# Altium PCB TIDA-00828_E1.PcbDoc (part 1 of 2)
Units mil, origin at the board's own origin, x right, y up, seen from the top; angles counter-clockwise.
Board outline 3410 x 2125 mil, 4 copper layers (Top Layer, Signal Layer 1, Signal Layer 2, Bottom Layer), stack 61.6 mil thick; 60 components, 54 nets, 228 pads, 108 vias.
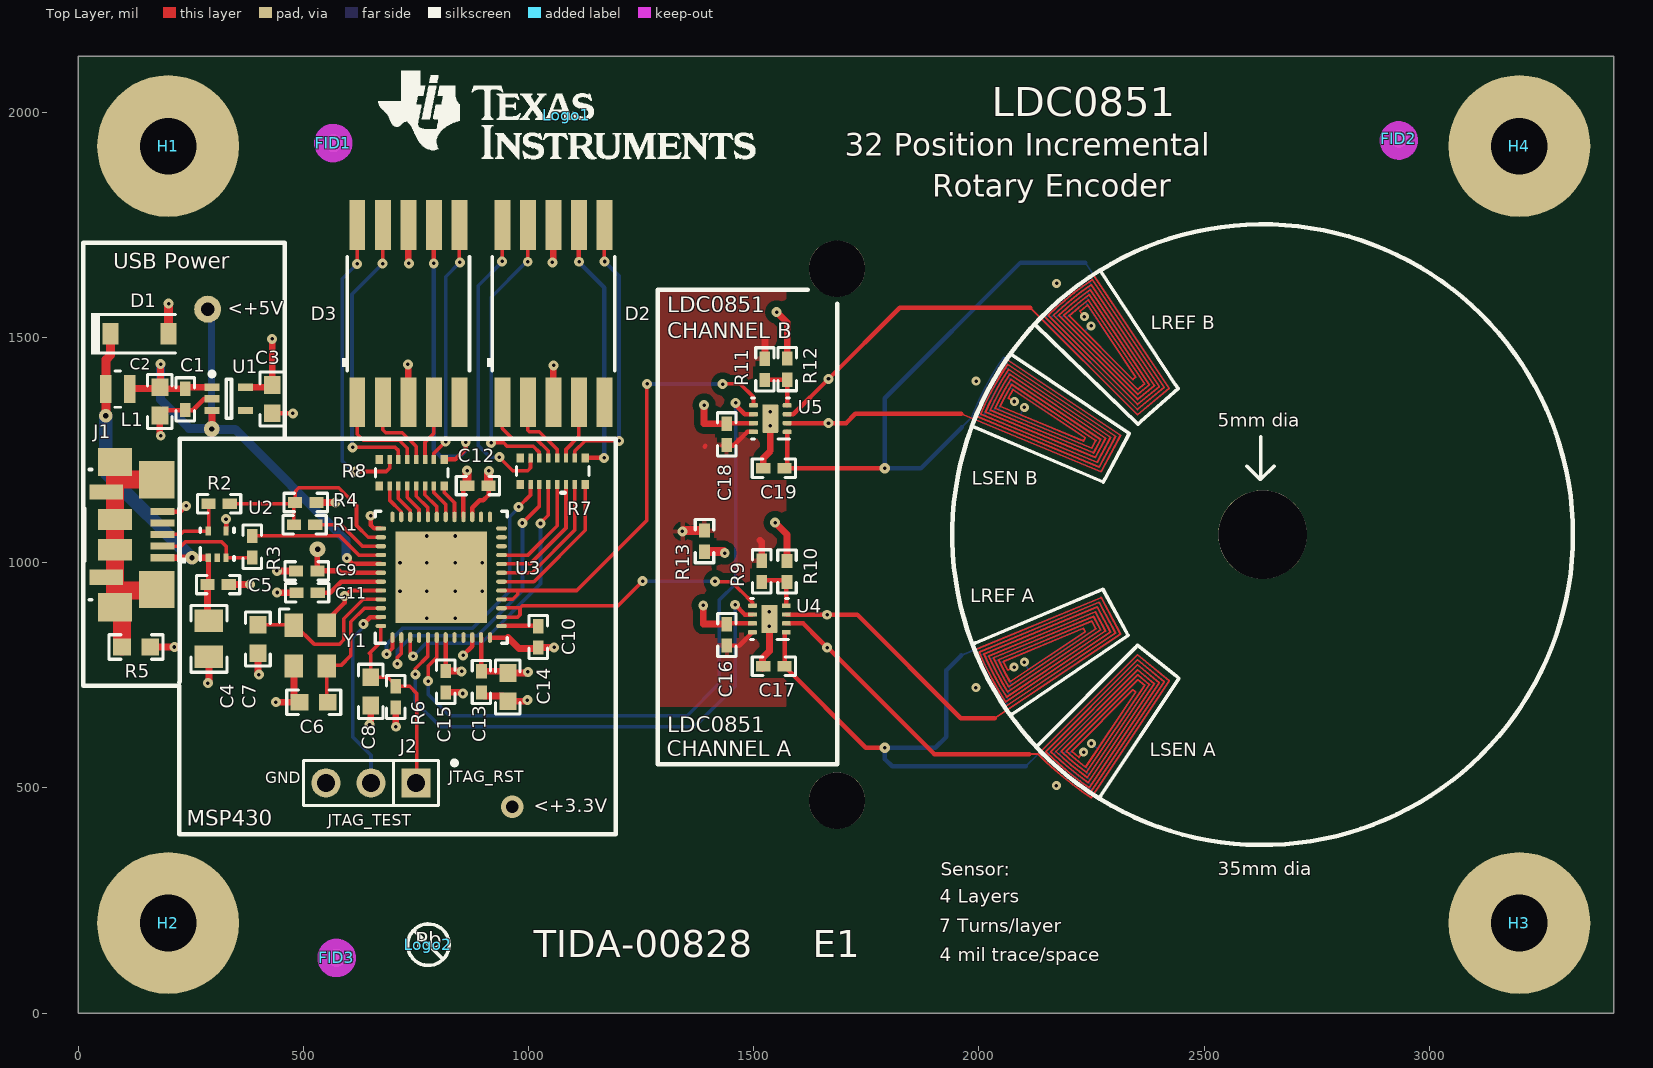
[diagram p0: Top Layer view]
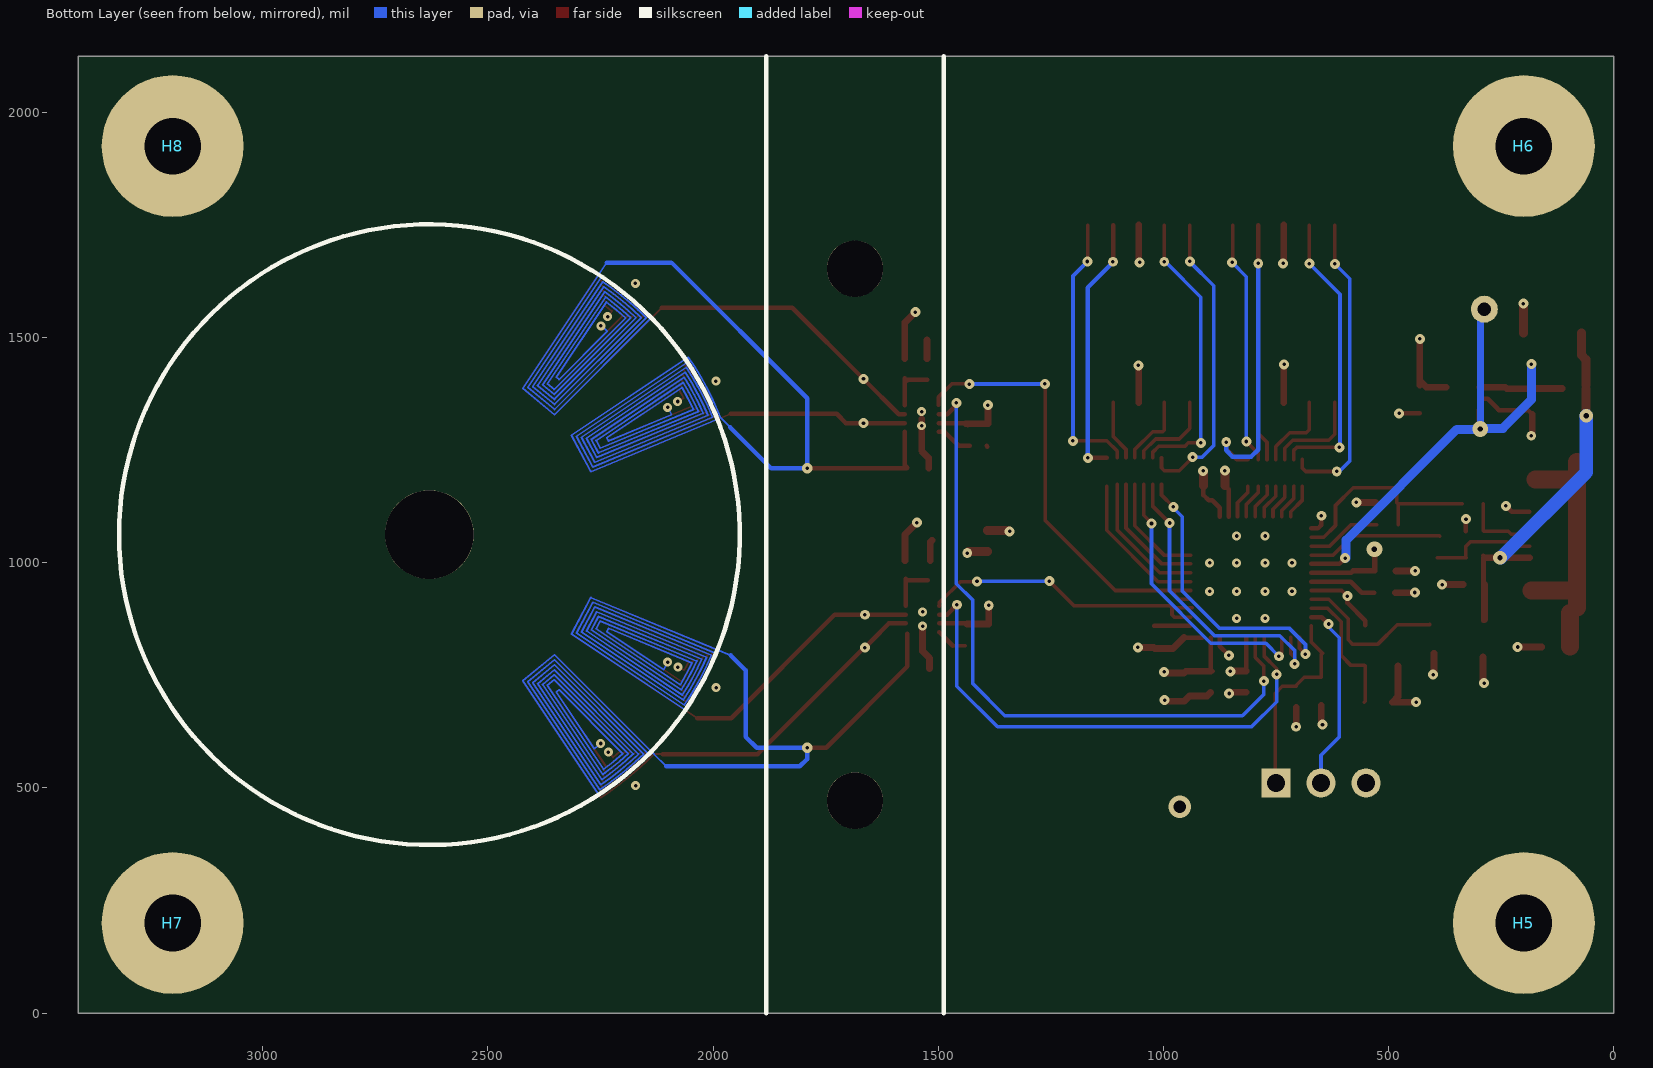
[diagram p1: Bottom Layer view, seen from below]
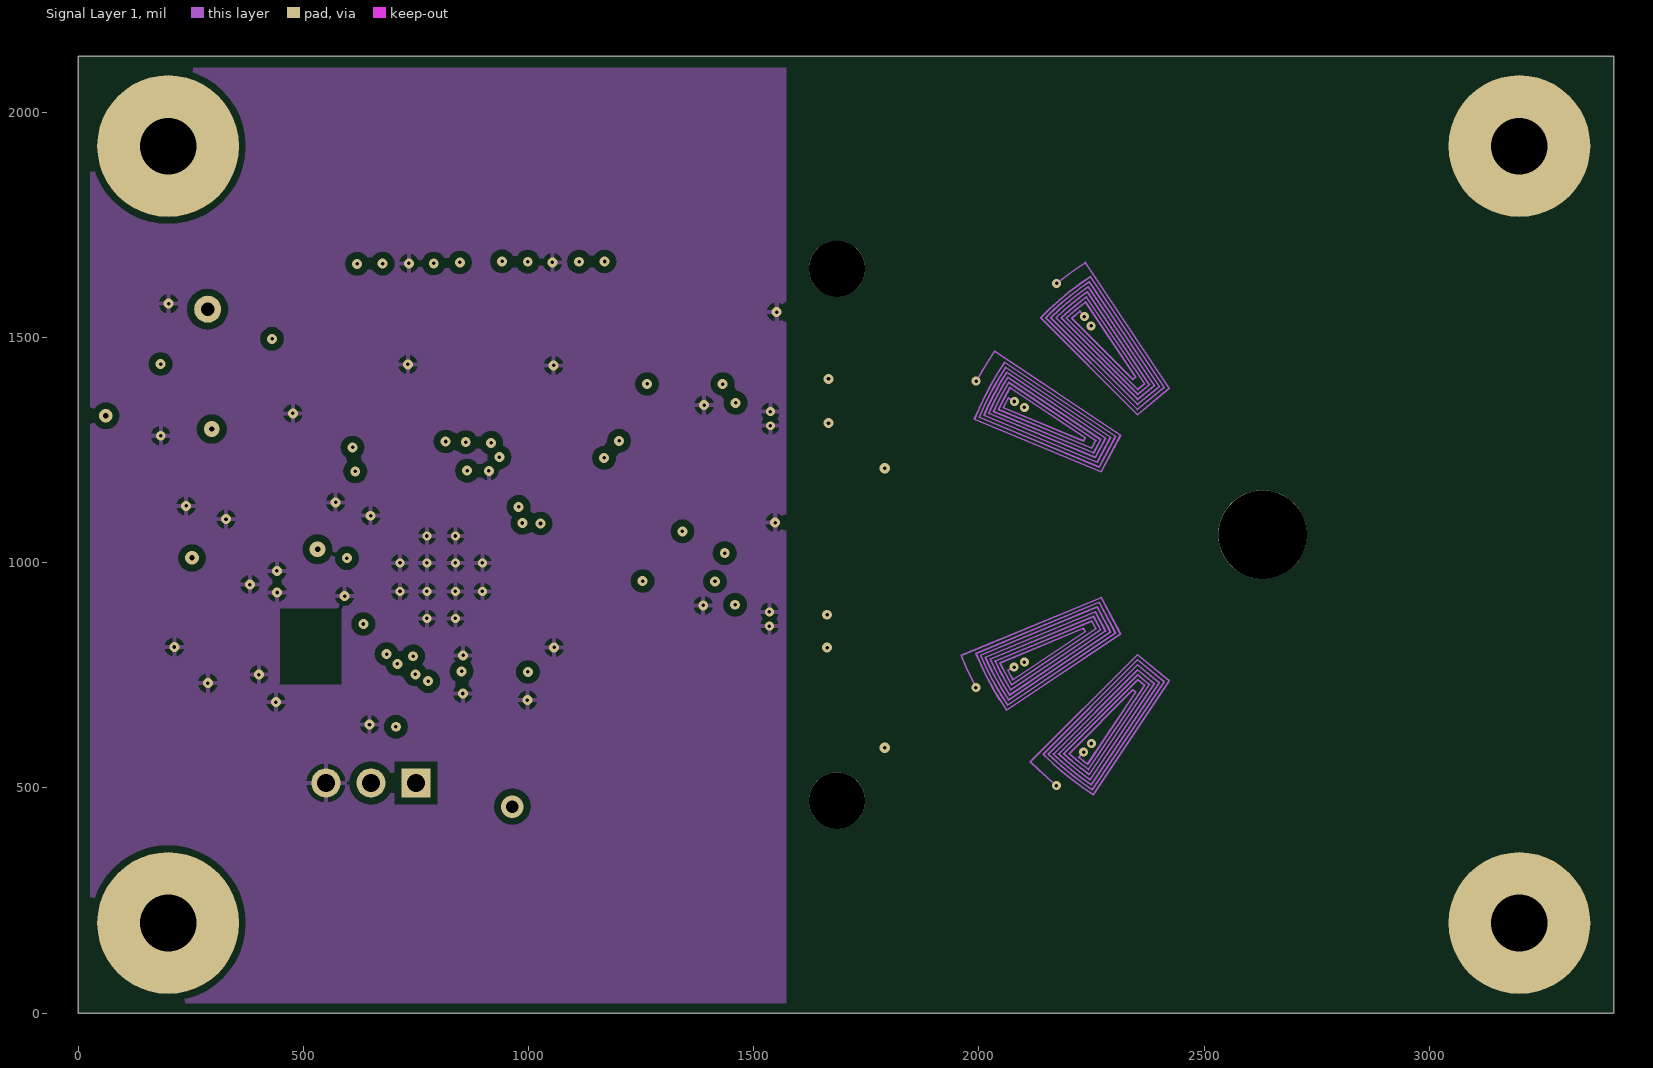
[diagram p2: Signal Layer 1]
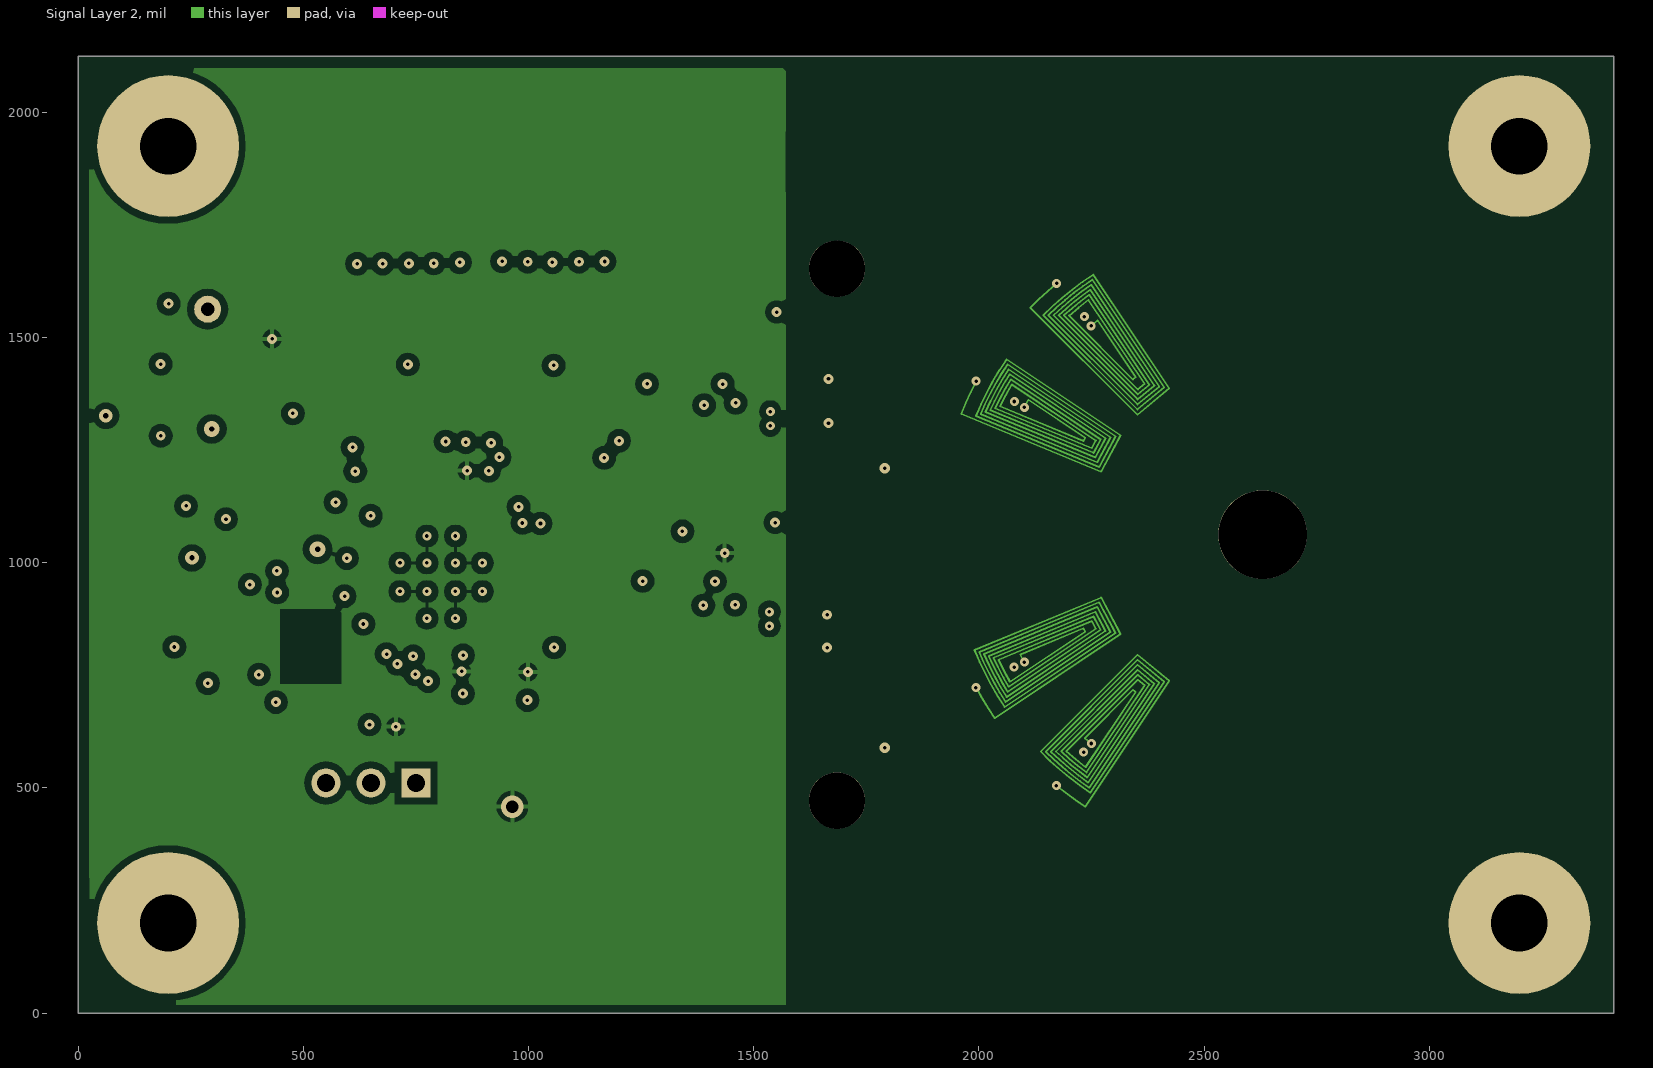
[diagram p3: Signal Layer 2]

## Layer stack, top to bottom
Top Solder: solder mask 0.4, Solder Resist, Dk 3.5
Top Layer: signal copper 1.4
Dielectric 1: core 10, FR-4, Dk 4.1
Signal Layer 1: signal copper 1.4
Dielectric 2: prepreg 36, FR-4, Dk 4.1
Signal Layer 2: signal copper 1.4
Dielectric 3: core 10, FR-4, Dk 4.1
Bottom Layer: signal copper 1.4
Bottom Solder: solder mask 0.4, Solder Resist, Dk 3.5

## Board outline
0,0 3410,0 3410,2125 0,2125

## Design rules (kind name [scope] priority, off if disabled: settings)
AcuteAngle [All] p1: minimum=4.50000000000000E+0001 checktracksonly=FALSE
AssemblyTestPointUsage [All] p1: valid=2
Clearance Clearance_Keepouts [((IsTrack Or IsArc) And Not InPoly) And IsFree and IsKeepOut vs ((IsTrack Or IsArc) And Not InPoly) And IsFree and IsKeepOut] p1: gap=0
Clearance Clearance_BoardEdge_MountingHoles [OnCopper and InComponentClass('Mounting Holes') vs IsKeepOut] p2: gap=40
Clearance Clearance_BoardEdge_Poly [OnCopper and InPoly vs IsKeepOut] p3: gap=25
Clearance Clearance_BoardEdge [OnCopper and Not InComponentClass('Logo') and not InComponentClass('FiducialMark') and not InRegion(1000,500,4000,800) and Not IsKeepout vs IsKeepOut] p4: gap=25
Clearance Clearance_Poly [InPolygon] p5: gap=15
Clearance [All] p6: gap=8 except(7: SMDPad-SMDPad)
ComponentClearance ComponentClearance_MountingHoles_FiducialMarks [InComponentClass('Mounting Holes') vs InComponentClass('FiducialMark')] p1: gap=50 collisioncheckmode=3 verticalgap=10 showdistances=FALSE
ComponentClearance ComponentClearance_Shunt [InComponentClass('Header') vs InComponentClass('Shunt')] p2: gap=0 collisioncheckmode=3 verticalgap=0 showdistances=FALSE
ComponentClearance ComponentClearance_Logo [InComponentClass('Logo')] p3: gap=50 collisioncheckmode=3 verticalgap=10 showdistances=FALSE
ComponentClearance ComponentClearance_ScrewToNut [(HasFootprint('NY PMS 440 0025 PH')) vs (HasFootprint('Keystone_1902C'))] p4: gap=5 collisioncheckmode=3 verticalgap=10 showdistances=FALSE
ComponentClearance ComponentClearance_MountingHoles [InComponentClass('Mounting Holes')] p5: gap=250 collisioncheckmode=3 verticalgap=100000 showdistances=FALSE
ComponentClearance ComponentClearance_SmallPassives [HasFootprint('0201*') or HasFootprint('0402*') or HasFootprint('0508') or HasFootprint('0603*') or HasFootprint('0612') or HasFootprint('0805*') or HasFootprint('0815*') or HasFootprint('0830*') or HasFootprint('1206*') or HasFootprint('1210*') or HasFootprint('1808*') or HasFootprint('1812*') or HasFootprint('1825*') or HasFootprint('2010*') or HasFootprint('2220*') or HasFootprint('2225*') or HasFootprint('2512*') or HasFootprint('2728*') or HasFootprint('3518*') vs HasFootprint('0201*') or HasFootprint('0402*') or HasFootprint('0508') or HasFootprint('0603*') or HasFootprint('0612') or HasFootprint('0805*') or HasFootprint('0815*') or HasFootprint('0830*') or HasFootprint('1206*') or HasFootprint('1210*') or HasFootprint('1808*') or HasFootprint('1812*') or HasFootprint('1825*') or HasFootprint('2010*') or HasFootprint('2220*') or HasFootprint('2225*') or HasFootprint('2512*') or HasFootprint('2728*') or HasFootprint('3518*')] p6: gap=20 collisioncheckmode=3 verticalgap=10 showdistances=FALSE
ComponentClearance ComponentClearance_THtoSMT [IsThruComponent vs IsSMTComponent] p7: gap=100 collisioncheckmode=3 verticalgap=30 showdistances=FALSE
ComponentClearance ComponentClearance_THtoTH [IsThruComponent vs IsThruComponent] p8: gap=118.11 collisioncheckmode=3 verticalgap=30 showdistances=FALSE
ComponentClearance [All] p9: gap=30 collisioncheckmode=3 verticalgap=10 showdistances=FALSE
DiffPairsRouting [All] p1: maxlimit=100 minlimit=10 mostfreqgap=10 toplayer_minwidth=15 toplayer_maxwidth=15 toplayer_prefwidth=15 midlayer1_minwidth=15 midlayer1_maxwidth=15 midlayer1_prefwidth=15 midlayer2_minwidth=15 midlayer2_maxwidth=15 midlayer2_prefwidth=15 bottomlayer_minwidth=15 bottomlayer_maxwidth=15 bottomlayer_prefwidth=15 maxuncoupledlength=1000
FabricationTestPointUsage TestPointUsage [All] p1: valid=2 allowmultiple=FALSE
FabricationTestpoint Testpoint [All] p1: side=3 testpointundercomponent=TRUE minsize=40 maxsize=100 preferedsize=60 minholesize=0 maxholesize=40 preferedholesize=32 testpointgrid=1 allowsidetop=TRUE allowsidebottom=TRUE usegrid=TRUE gridtolerance=0.01
FanoutControl Fanout_LCC [IsLCC] p1: bgadir=Out bgaviamode=Centered fanoutstyle=Auto fanoutdirection=Alternating viagrid=1 // Fanout_LCC (Default Rule)
FanoutControl Fanout_BGA [IsBGA] p2: bgadir=Out bgaviamode=Centered fanoutstyle=Auto fanoutdirection=Alternating viagrid=1 // Fanout_BGA (Default Rule)
FanoutControl Fanout_Default [All] p4: bgadir=Out bgaviamode=Centered fanoutstyle=Auto fanoutdirection=Alternating viagrid=1 // Fanout_Default (Default Rule)
FanoutControl Fanout_Small [(CompPinCount < 5)] p5: bgadir=Out bgaviamode=Centered fanoutstyle=Auto fanoutdirection=OutThenIn viagrid=1 // Fanout_Small (Default Rule)
HoleSize [All] p1: absolutevalues=TRUE maxlimit=251 minlimit=8 maxpercent=80.000 minpercent=20.000
MinimumAnnularRing MinimumAnnularRing_ThermalPadVias [IsVia and InAnyComponent] p1: minimumring=5.91
MinimumAnnularRing [All] p2: minimumring=6
MinimumSolderMaskSliver MinimumSolderMaskSliver_Logo [InComponentClass('Logo') vs InComponentClass('Logo')] p1: minsoldermaskwidth=0.7
MinimumSolderMaskSliver [All] p2: minsoldermaskwidth=3.94
PlaneConnect [All] p1: planeconnectstyle=Relief reliefexpansion=10 reliefentries=4 reliefconductorwidth=10 reliefairgap=10
PolygonConnect [All] p1: connectstyle=Relief reliefconductorwidth=10 reliefentries=4 polygonreliefangle="90 Angle" airgapwidth=10
RoutingVias ThermalPadVias [IsVia and InAnyComponent] p1: holewidth=7.87 width=19.68 viastyle="Through Hole" minholewidth=7.87 minwidth=19.68 maxholewidth=12.99 maxwidth=23.62
RoutingVias [All] p2: holewidth=8 width=22 viastyle="Through Hole" minholewidth=7.87 minwidth=20 maxholewidth=40 maxwidth=65
SilkToBoardRegionClearance [Not ((IsComment or IsDesignator) And (Hide <> 'False')) and not InRegion(1000,500,4000,800)] p1:
SilkToSilkClearance SilkToSilkClearance_Pb-FreeLogo [(HasFootprint('Pb-Free_Overlay_Medium') OR HasFootprint('Pb-Free_Overlay_Small')) vs (HasFootprint('Pb-Free_Overlay_Medium') OR HasFootprint('Pb-Free_Overlay_Small'))] p1: silktosilkclearance=0
SilkToSilkClearance [All] p2: silktosilkclearance=4
SilkToSolderMaskClearance SilkToComonentPadClearance [IsPad and InAnycomponent] p1: minsilkscreentomaskgap=1 clearancetoexposedcopper=TRUE
SilkToSolderMaskClearance "Silk to Solder Mask Opening" [All] p2: minsilkscreentomaskgap=1 clearancetoexposedcopper=FALSE
SolderMaskExpansion [All] p1: expansion=1.97
UnpouredPolygon [All] p1: allowunpoured=FALSE
Width [All] p1: maxlimit=100 minlimit=4 preferedwidth=8 minimp=50.000000 maximp=50.000000 favimp=50.000000 checkconnectedcopper=TRUE
14 further rules are at their usual default settings.

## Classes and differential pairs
component class "Mounting Holes": H1 H2 H3 H4
component class Header: J2
component class Logo: Logo1
component class FiducialMark: FID1 FID2 FID3
component class AssemblyNote: ZZ1 ZZ2 ZZ3

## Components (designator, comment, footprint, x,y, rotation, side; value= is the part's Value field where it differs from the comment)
C1 "GRM155R71C104JA88D" 0402 237.8,1362.73 r270 top
C2 "C1608X5R1A106M" 0603 181.61,1358.34 r270 top
C3 "C0603C225K8PACTU" 0603 431.14,1363.24 r270 top
C4 "C2012X5R1C226K125AC" 0805_HV 290.51,831.02 r270 top
C5 "GRM155R71C104JA88D" 0402 311.08,951.59 r0 top
C6 "GRM1885C2A180JA01D" 0603 523.17,690.17 r0 top
C7 "GRM1885C2A180JA01D" 0603 399.42,830.82 r90 top
C8 "C0603X222K5RACTU" 0603 649.76,714.59 r90 top
C9 "C1005X7R1A224K050BB" 0402 507.74,981.82 r180 top
C10 "GRM155R60J474KE19D" 0402 1021.53,835.29 r270 top
C11 "C1005X7R1A224K050BB" 0402 508.46,933.41 r180 top
C12 "GRM155R71C104JA88D" 0402 887.71,1171.37 r0 top
C13 "GRM155R71C104JA88D" 0402 895.61,735.37 r270 top
C14 "C1608X5R1A106M" 0603 954.3,723.89 r270 top
C15 "GRM155R71C104JA88D" 0402 816.3,735.89 r270 top
C16 "GRM155R71C104KA88D" 0402 1440.64,839.71 r90 top
C17 "GRM1555C1H620JA01D" 0402 1545,770 r180 top
C18 "GRM155R71C104KA88D" 0402 1440,1285 r90 top
C19 "GRM1555C1H620JA01D" 0402 1545,1210 r180 top
D1 "MMSZ5232B-7-F" SOD-123 136.49,1508.49 r0 top
D2 "ACSC02-41SURKWA-F01" ACSC02-41_Red 1055.3,1552.89 r90 top
D3 "ACSC02-41SURKWA-F01" ACSC02-41_Red 733.3,1552.89 r90 top
FID1 "Fiducial" Fiducial10-20#1 566.75,1931.79 r0 top
FID2 "Fiducial" Fiducial10-20#2 2932.4,1937.58 r0 top
FID3 "Fiducial" Fiducial10-20#1 574.01,122.63 r0 top
H1 "NY PMS 440 0025 PH" "NY PMS 440 0025 PH" 200,1925 r0 top
H2 "NY PMS 440 0025 PH" "NY PMS 440 0025 PH" 200,200 r0 top
H3 "NY PMS 440 0025 PH" "NY PMS 440 0025 PH" 3200,200 r0 top
H4 "NY PMS 440 0025 PH" "NY PMS 440 0025 PH" 3200,1925 r0 top
H5 "1902C" Keystone_1902C 200,200 r180 bottom
H6 "1902C" Keystone_1902C 200,1925 r180 bottom
H7 "1902C" Keystone_1902C 3200,200 r180 bottom
H8 "1902C" Keystone_1902C 3200,1925 r180 bottom
J1 "ZX62R-B-5P" Hirose_ZX62R-B-5P 82,1062.4 r180 top
J2 "TSW-103-07-G-S" TSW-103-07-G-S 650.34,511.15 r180 top
L1 "VLS201610ET-100M" VLS201610ET 88.39,1385.65 r0 top
Logo1 "Texas Instruments" TI_Stacked_Overlay_Small 1085.32,1994.06 r0 top
Logo2 "Pb-Free Symbol" Pb-Free_Overlay_Small 777.78,151.96 r0 top
R1 "CRCW04021K50JNED" 0402 502.95,1084.39 r0 top
R2 "CRCW040210R0FKED" 0402 313.38,1131.12 r0 top
R3 "CRCW040210R0FKED" 0402 387,1035.61 r90 top
R4 "RC0402JR-071ML" 0402 505.58,1133.82 r180 top
R5 "CRCW060333R0JNEA" 0603 129,813 r180 top
R6 "CRCW040233K0JNED" 0402 705.29,702.02 r90 top
R7 "EXB-2HV221JV" RESCAXS_EXB-2HV 1053.83,1203.42 r180 top
R8 "EXB-2HV221JV" RESCAXS_EXB-2HV 740.86,1199.81 r180 top
R9 "CRCW040253K6FKED" 0402 1517.96,980.86 r90 top
R10 "RC0402JR-070RL" 0402 1573.96,980.6 r270 top
R11 "CRCW040253K6FKED" 0402 1525,1429.41 r90 top
R12 "RC0402JR-070RL" 0402 1574.39,1429.75 r270 top
R13 "RC0402JR-070RL" 0402 1390.84,1048.11 r270 top
U1 "LP5951MG-3.3/NOPB" MAA05A_N 334.76,1364.08 r0 top
U2 "TPD2E001DRLR" DRL0005A 308.81,1040.63 r90 top
U3 "MSP430F5500IRGZR" RGZ0048A 806.3,967.89 r90 top
U4 "LDC0851DSGR" DSG0008A 1535,875.25 r180 top
U5 "LDC0851DSGR" DSG0008A 1537,1320 r180 top
Y1 "ABM8-24.000MHZ-B2-T" XTAL_ABM8 515.6,816.03 r0 top
ZZ1 "This Assembly Note is for PCB labels only" AssemblyNoteLabel 186,3858 r0 top
ZZ2 "These assemblies are ESD sensitive, ESD precautions shall be observed." AssemblyNote 185,3740.56 r0 top
ZZ3 "These assemblies must be clean and free from flux and all contaminants. Use of no clean flux is not acceptable." AssemblyNote 185,3652 r0 top

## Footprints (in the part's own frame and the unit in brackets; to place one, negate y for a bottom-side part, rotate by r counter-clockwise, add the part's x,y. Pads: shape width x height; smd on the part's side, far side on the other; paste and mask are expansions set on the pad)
0402 [mm] "0402 from SM-752 data"
  rect 0.8x0.6 smd: 1(-0.6,0) 2(0.6,0)
  silkscreen extent -1.22,-0.52 1.22,0.52, body extent -0.55,-0.3 0.55,0.3, height 0.6
0603 [mm] "0603 from SM-752 data"
  rect 1x0.95 smd: 1(-0.8,0) 2(0.8,0)
  silkscreen extent -1.52,-0.69 1.52,0.69, body extent -0.87,-0.47 0.87,0.47, height 1
0805_HV [mil] "0805 with 30mil clearance between pads"
  rect 50x63 smd: 1(-40,0) 2(40,0)
  silkscreen extent -74,-40 74,40, body extent -43,-29 43,29, height 57
ACSC02-41_Red [mm] "SMT, 10-Leads, Body 6.9x10mm, Pitch 1.44mm"
  rect 2.8x0.9 smd: 1(-5,2.88) 2(-5,1.44) 3(-5,0) 4(-5,-1.44) 5(-5,-2.88) 6(5,-2.88) 7(5,-1.44) 8(5,0) 9(5,1.44) 10(5,2.88)
  silkscreen extent -3.22,-3.45 3.22,3.75, body extent -5,-3.45 5,3.45, height 3.01
AssemblyNote [mil] "Assembly Note"
AssemblyNoteLabel [mil] "Assembly Note for PCB Labels"
DRL0005A [mm] "SOTFL, 5-Flat Leads, Body 1.2x1.6x0.6mm, Pitch 0.5mm, TI recommended"
  rect 0.5x0.3 smd: 1(-0.75,0.5) 2(-0.75,0) 3(-0.75,-0.5) 4(0.75,-0.5) 5(0.75,0.5)
  silkscreen extent -0.9,-0.95 0.9,0.95, body extent -0.85,-0.85 0.85,0.85, height 0.62
DSG0008A [mm] "SON, 8-Leads, Body 2x2mm, Pitch 0.5mm, Thermal Pad 1.6x0.9mm, TI Recommended"
  rrect40% 0.5x0.25 smd: 1(-0.95,0.75) 2(-0.95,0.25) 3(-0.95,-0.25) 4(-0.95,-0.75) 5(0.95,-0.75) 6(0.95,-0.25) 7(0.95,0.25) 8(0.95,0.75)
  rrect11% 0.9x1.6 smd paste-0.45: 9(0,0)
  silkscreen extent -1.07,-1.15 1.07,1.15, body extent -1.05,-1.05 1.05,1.05, height 0.8
Fiducial10-20#1 [mm]
  round 1 smd mask+0.5: 1(0,0)
  Top Layer keep-out circle w1.178: c0,0 r0.5
Fiducial10-20#2 [mm]
  round 1 smd mask+0.5: 1(0,0.097)
  Top Layer keep-out circle w1.178: c0,0 r0.5
Hirose_ZX62R-B-5P [mm] "Hirose"
  rect 1.35x0.4 smd: 1(-2.68,1.3) 2(-2.68,0.65) 3(-2.68,0) 4(-2.68,-0.65) 5(-2.68,-1.3)
  rect 2x2.1 smd: 6(-2.35,-3.1) 7(-2.35,3.1)
  rect 1.9x1.6 smd: 8(0,-4.1) 13(0,4.1)
  rect 1.88x0.85 smd: 9(0.495,-2.4) 12(0.495,2.4)
  rect 1.9x1.2 smd: 10(0,-0.85) 11(0,0.85)
  silkscreen extent -4,-3.67 1.7,3.67, body extent -2.57,-3.48 2.11,3.45, height 2.65
Keystone_1902C [mil] "Hex Standoff, 4-40 threaded, nylon"
  round 1 on Mech4: 0(0,0)
  body extent -145,-126 146,126, height 501
MAA05A_N [mm] "SOT353, 5-Leads, Body 2x1.3mm, Pitch 0.65mm, Lead Span 2.1mm, IPC Medium Density"
  rect 0.85x0.4 smd: 1(-0.95,0.65) 2(-0.95,0) 3(-0.95,-0.65) 4(0.95,-0.65) 5(0.95,0.65)
  silkscreen extent -1.07,-1.1 0.15,1.52, body extent -0.7,-1.1 0.7,1.1, height 1.1
"NY PMS 440 0025 PH" [mm] "4-40 nylon screw and mounting hole"
  round 8 hole 3.2: 1(0,0)
  body extent -3.3,-3.3 3.3,3.3, height 2.69
Pb-Free_Overlay_Small [mil]
  silkscreen extent -46,-46 46,46
RESCAXS_EXB-2HV [mm] "Panasonic Resistor Array"
  rect 0.425x0.5 smd mask+0.07: 1(-1.837,-0.75) 8(1.837,-0.75) 9(1.837,0.75) 16(-1.837,0.75)
  rect 0.25x0.5 smd mask+0.07: 2(-1.25,-0.75) 3(-0.75,-0.75) 4(-0.25,-0.75) 5(0.25,-0.75) 6(0.75,-0.75) 7(1.25,-0.75) 10(1.25,0.75) 11(0.75,0.75) 12(0.25,0.75) 13(-0.25,0.75) 14(-0.75,0.75) 15(-1.25,0.75)
  silkscreen extent -2.05,-0.25 2.05,0.25, body extent -1.95,-0.8 1.95,0.8, height 0.55
RGZ0048A [mm] "QFN, 48-Leads, Body 7x7mm, Pitch 0.5mm, Thermal Pad 5.15X5.15mm, TI recommended"
  oval 0.6x0.24 smd: 1(-3.4,2.75) 2(-3.4,2.25) 3(-3.4,1.75) 4(-3.4,1.25) 5(-3.4,0.75) 6(-3.4,0.25) 7(-3.4,-0.25) 8(-3.4,-0.75) 9(-3.4,-1.25) 10(-3.4,-1.75) 11(-3.4,-2.25) 12(-3.4,-2.75) 25(3.4,-2.75) 26(3.4,-2.25) 27(3.4,-1.75) 28(3.4,-1.25) 29(3.4,-0.75) 30(3.4,-0.25) 31(3.4,0.25) 32(3.4,0.75) 33(3.4,1.25) 34(3.4,1.75) 35(3.4,2.25) 36(3.4,2.75)
  oval 0.24x0.6 smd: 13(-2.75,-3.4) 14(-2.25,-3.4) 15(-1.75,-3.4) 16(-1.25,-3.4) 17(-0.75,-3.4) 18(-0.25,-3.4) 19(0.25,-3.4) 20(0.75,-3.4) 21(1.25,-3.4) 22(1.75,-3.4) 23(2.25,-3.4) 24(2.75,-3.4) 37(2.75,3.4) 38(2.25,3.4) 39(1.75,3.4) 40(1.25,3.4) 41(0.75,3.4) 42(0.25,3.4) 43(-0.25,3.4) 44(-0.75,3.4) 45(-1.25,3.4) 46(-1.75,3.4) 47(-2.25,3.4) 48(-2.75,3.4)
  rect 5.15x5.15 smd paste-2.6: 49(0,0)
  silkscreen extent -3.72,-3.72 3.72,3.72, body extent -3.58,-3.57 3.57,3.58, height 1.01
SOD-123 [mm] "On Semi recommended land pattern"
  rect 0.915x1.22 smd: 1(-1.637,0) 2(1.637,0)
  silkscreen extent -2.74,-1.17 2.03,1.17, body extent -1.93,-0.9 1.93,0.9, height 1.35
TI_Stacked_Overlay_Small [mil]
  silkscreen extent -418,-98 418,98
TSW-103-07-G-S [mm] "Samtec 100mil, 1x3, 230 mil above insulator"
  rect 1.65x1.65 hole 1.016: 1(-2.54,0)
  round 1.65 hole 1.016: 2(0,0) 3(2.54,0)
  silkscreen extent -4.84,-1.27 3.81,1.27, body extent -3.81,-1.27 3.81,1.27, height 8.38
VLS201610ET [mm] "TDK"
  rect 0.65x1.6 smd: 1(-0.675,0) 2(0.675,0)
  silkscreen extent -0.15,-1.02 0.15,1.02, body extent -1.05,-0.85 1.05,0.85, height 0.95
XTAL_ABM8 [mm] "Abracon recommended land pattern"
  rect 1.05x1.3 smd: 1(-0.925,1.15) 2(-0.925,-1.15) 3(0.925,-1.15) 4(0.925,1.15)
  silkscreen extent -1.73,1.3 -1.2,2.07, body extent -1.35,-1.7 1.35,1.7, height 0.8

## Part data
C1 C5 C12 C13 C15: library part 0402YC132KAT2A, "CAP CER 0.1UF 16V 5% X7R 0402"
C2 C14: "CAP, CERM, 10uF, 10V, +/-20%, X5R, 0603"
C3: "CAP, CERM, 2.2uF, 10V, +/-10%, X5R, 0603"
C4: "CAP, CERM, 22uF, 16V, +/-10%, X5R, 0805"
C6 C7: "CAP, CERM, 18pF, 100V, +/-5%, C0G/NP0, 0603"
C8: "CAP, CERM, 2200pF, 50V, +/-10%, X7R, 0603"
C9 C11: library part 0402YC132KAT2A, "CAP, CERM, 220nF, 10V, 10%, X7R, 0402"
C10: "CAP, CERM, 0.47 µF, 6.3 V, +/- 10%, X5R, 0402"
C16 C18: "CAP, CERM, 0.1 µF, 16 V, +/- 10%, X7R, 0402"
C17 C19: "CAP, CERM, 62 pF, 50 V, +/- 5%, C0G/NP0, 0402"
D1: "Diode, Zener, 5.6V, 500mW, SOD-123"
D2 D3: "LED, Red, SMD"
FID1 FID2 FID3: "Fiducial mark.  There is nothing to buy or mount."
H1 H2 H3 H4: "Machine Screw, Round, #4-40 x 1/4, Nylon, Philips panhead"
H5 H6 H7 H8: "Standoff, Hex, 0.5\"L #4-40 Nylon"
J1: "Connector, Receptacle, Micro-USB Type B, SMT"
J2: "Header, 100mil, 3x1, Gold, TH"
L1: "Inductor, Shielded, Ferrite, 10 µH, 0.4 A, 1.38 ohm, SMD"
Logo1: library part TI_Logo, "Texas Instrument Corporate Signature"
Logo2: library part Pb-Free
R1: library part CRCW040233K0JNED, "RES 1.5K OHM 1/16W 5% 0402 SMD"
R2 R3: "RES, 10.0, 1%, 0.063 W, 0402"
R4: library part CRCW040233K0JNED, "RES,1M ohm, 5%, 0.063W, 0402"
R5: "RES, 33 ohm, 5%, 0.1W, 0603"
R6: "RES, 33k ohm, 5%, 0.063W, 0402"
R7 R8: library part EXB-2HV681JV, "RES, 220, 5%, 0.0625 W, Resistor Array - 8x1"
R9 R11: "RES, 53.6 k, 1%, 0.063 W, 0402"
R10 R12 R13: "RES, 0, 5%, 0.063 W, 0402"
U1: "Micropower, 150mA Low-Dropout CMOS Voltage Regulator, 5-pin SC-70, Pb-Free"
U2: "Low-Capacitance + / - 15 kV ESD-Protection Array for High-Speed Data Interfaces, 2 Channels, -40 to +85 degC, 5-pin SOT (DRL), Green (RoHS & no Sb/Br)"
U3: "25 MHz Mixed Signal Microcontroller with 8 KB Flash, 4096 B SRAM and 31 GPIOs, -40 to 85 degC, 48-pin QFN (RGZ), Green (RoHS & no Sb/Br)"
U4 U5: "1.8-3.3V Inductive Switch, DSG0008A"
Y1: "Crystal, 24.000MHz, 18pF, SMD"
ZZ1: library part AssemblyNoteLabel
ZZ2 ZZ3: library part AssemblyNote

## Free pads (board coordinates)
  round 60 hole 30: 0(287.81,1562.89)
  round 125 hole 125 unplated: 0(1685.12,471.85) 0(1685.12,1652.95)
  round 197 hole 197 unplated: 0(2630,1062.4)

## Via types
v1: diameter 22, hole 7.87, Top Layer to Bottom Layer, tented both sides, 64 vias
v2: diameter 19.68, hole 7.87, Top Layer to Bottom Layer, 16 vias
v3: diameter 20, hole 7.87, Top Layer to Bottom Layer, tented both sides, 12 vias
v4: diameter 22, hole 7.87, Top Layer to Bottom Layer, 9 vias
v5: diameter 30, hole 12, Top Layer to Bottom Layer, tented both sides, 2 vias
v6: diameter 24, hole 7.87, Top Layer to Bottom Layer, 2 vias
v7: diameter 35, hole 12, Top Layer to Bottom Layer, tented both sides, 1 vias
v8: diameter 50, hole 28, Top Layer to Bottom Layer, 1 vias
v9: diameter 35, hole 12, Top Layer to Bottom Layer, 1 vias

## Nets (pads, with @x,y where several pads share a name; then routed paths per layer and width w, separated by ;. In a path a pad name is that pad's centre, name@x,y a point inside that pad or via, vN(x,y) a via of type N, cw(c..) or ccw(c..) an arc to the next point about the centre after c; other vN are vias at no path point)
7SEG-A: R7.16 U3.18 | length 331.1
  Top Layer w8: U3.18@940.16,958.05 1012.09,958.05 1126.3,1072.26 R7.16@1126.3,1169.89
7SEG-A2: R8.16 U3.29 | length 77.9
  Top Layer w8: R8.16@813.2,1170.28 813.2,1155.79 835.83,1133.17 U3.29@835.83,1101.75
7SEG-B: R7.15 U3.19 | length 303.5
  Top Layer w8: U3.19@940.16,977.73 1008.21,977.73 1103.04,1072.57 R7.15@1103.04,1173.89
7SEG-B2: R8.15 U3.30 | length 79.3
  Top Layer w8: R8.15@790.07,1170.28 790.07,1155.59 816.14,1129.52 U3.30@816.14,1101.75
7SEG-C: R7.14 U3.20 | length 272.9
  Top Layer w8: U3.20@940.16,997.42 1003.54,997.42 1083.35,1077.23 R7.14@1083.35,1173.89
7SEG-C2: R8.14 U3.31 | length 79.6
  Top Layer w8: R8.14@770.39,1170.28 770.07,1169.96 770.07,1151.23 796.46,1124.84 U3.31@796.46,1101.75
7SEG-D: R7.13 U3.21 | length 242.3
  Top Layer w8: U3.21@940.16,1017.1 998.88,1017.1 1063.67,1081.89 R7.13@1063.67,1173.89
7SEG-D2: R8.13 U3.32 | length 79.3
  Top Layer w8: R8.13@750.7,1170.28 750.7,1147.97 776.77,1121.9 U3.32@776.77,1101.75
7SEG-E: R7.12 U3.3 | length 621.6
  Top Layer w8: U3.3@737.4,834.03 737.4,799.02 v1(743.94,792.48) ; v1(1026.78,1087.13) 1026.78,1088.55 1043.98,1105.75 R7.12@1043.98,1173.89
  Bottom Layer w8: v1(743.94,792.48) 772.73,821.27 894.98,821.27 1026.78,953.06 v1(1026.78,1087.13)
7SEG-E2: R8.12 U3.33 | length 79.3
  Top Layer w8: R8.12@731.02,1170.28 731.02,1145.03 757.09,1118.96 U3.33@757.09,1101.75
7SEG-F: R7.11 U3.2 | length 676.3
  Top Layer w8: v1(708.88,775.52) 708.88,789.6 717.72,798.43 U3.2@717.72,834.03 ; v1(986.67,1088.32) 1024.3,1125.95 R7.11@1024.3,1173.89
  Bottom Layer w8: v1(708.88,775.52) 708.88,805.3 741.77,838.2 887.01,838.2 986.67,937.87 v1(986.67,1088.32)
7SEG-F2: R8.11 U3.34 | length 80
  Top Layer w8: R8.11@711.33,1170.28 710.53,1169.47 710.53,1142.89 737.4,1116.02 U3.34@737.4,1101.75
7SEG-G: R7.10 U3.1 | length 641.7
  Top Layer w8: v1(684.92,797.38) 698.03,810.49 U3.1@698.03,834.03 ; v1(978.14,1124.04) 1004.61,1150.52 R7.10@1004.61,1173.89
  Bottom Layer w8: v1(684.92,797.38) 684.92,818.7 720.42,854.2 875.23,854.2 958.37,937.34 958.37,1102.18 978.14,1121.95 v1(978.14,1124.04)
7SEG-G2: R8.10 U3.35 | length 79.3
  Top Layer w8: R8.10@691.65,1170.28 691.65,1139.14 717.72,1113.07 U3.35@717.72,1101.75
0851VDD: C16.1 C18.1 R9.2 R11.2 R13.1 U4.8 U5.8 | length 291.7
  Top Layer w8: C16.1@1440.64,816.08 1467.96,816.08
  Top Layer w10: 1391,1258 1392.38,1259.38 ; C18.1@1430,1260 1455,1260 1485.47,1290.47 U5.8@1499.6,1290.47 ; 1467.96,816.08 U4.8@1497.6,845.72
  Top Layer w15: 1514.14,1049.71 1517.96,1045.9 R9.2@1517.96,1004.48 ; R11.2@1525,1453.03 1525,1494.41
  Top Layer w20: v4(1341.9,1069.62) 1344.34,1072.06 1390.51,1072.06 R13.1@1390.84,1071.73
+3.3V: C3.1 C12.1 C13.1 C14.1 C15.1 R6.1 R13.2 U1.5 U3.7 U3.11 U3.28 | length 654.4
  Top Layer w10: U3.7@816.14,834.03 816.14,759.67 C15.1@816.3,759.51 ; U3.28@855.51,1101.75 855.51,1162.79 C12.1@864.09,1171.37 ; v1@863.55,1205.63 v1@864.09,1205.09 ; C13.1@891.3,759.51 894.88,763.1 U3.11@894.88,834.03 ; C14.1@950.7,758.99 C14.1@954.3,755.39 ; v1@1432.66,1024.49 v1(1435.73,1021.42)
  Top Layer w15: U1.5@372.16,1389.67 416.45,1389.67 C3.1@430.38,1403.6 ; v1(430.73,1497.05) 431.14,1496.64 C3.1@431.14,1394.73 ; R6.1@705.29,678.4 705.29,636.35 v1(705.7,635.95) ; C15.1@816.3,759.51 850.67,759.51 v1(851.48,758.71) ; C13.1@895.61,758.99 C14.1@950.7,758.99 ; C14.1@954.3,755.39 996.5,755.39 v1(998.65,757.54)
  Top Layer w20: C12.1@864.09,1171.37 v1@864.09,1205.09 ; R13.2@1390.84,1024.49 v1@1432.66,1024.49
  other v1: 863.9,1204.4
  other v8: 964.25,458.69
+5V: C1.1 C2.1 L1.2 pad.0@287.81,1562.89 U1.1 U1.3 U3.41 | length 1261.6
  Top Layer w10: v1(596.89,1010.25) 597.26,1010.25 610.09,997.42 U3.41@672.44,997.42
  Top Layer w15: L1.2@114.85,1386.76 182.51,1386.76 188.09,1386.35 C1.1@237.8,1386.35 241.11,1389.67 U1.1@297.35,1389.67 ; C2.1@181.61,1392.83 183.28,1394.5 v1(183.28,1441.1) ; v7@297.35,1307.7 U1.3@297.35,1338.49
  Bottom Layer w15: pad.0@287.81,1562.89 296.56,1554.15 v7@296.56,1308.5 ; v7@306.64,1298.42 v7@309.09,1295.97
  Bottom Layer w20: v1(183.28,1441.1) 183.28,1362 246.86,1298.42 v7@306.64,1298.42 ; v7@309.09,1295.97 348.73,1295.97 594.51,1050.19 v1@594.51,1010.55
  other v7: 296.85,1297.02
ADJ-A: R9.1 R10.2 U4.4 | length 103.5
  Top Layer w10: R9.1@1523,961.63 R10.2@1566.62,961.63 ; U4.4@1572.4,904.78 R10.2@1572.4,964.65
ADJ-B: R11.1 R12.2 U5.4 | length 106.3
  Top Layer w10: R11.1@1525,1405.79 1568.62,1405.79 R12.2@1570,1404.41 ; U5.4@1574.4,1349.53 R12.2@1574.4,1409.4 ; R12.2@1574.4,1408.81 R12.2@1575,1409.41
EN_A: U3.5 U4.6 | length 1153.1
  Top Layer w8: v1(748.96,752.04) 748.96,764.96 776.77,792.78 U3.5@776.77,834.03
  Top Layer w10: v1(1458.83,906.73) 1480.46,885.09 U4.6@1497.6,885.09
  Bottom Layer w8: v1(748.96,752.04) 748.96,691.37 804.69,635.63 1368.52,635.63 1458.83,725.94 v1(1458.83,906.73)
EN_B: U3.6 U5.6 | length 1515.7
  Top Layer w8: v1(777.17,737.25) 777.17,770.55 796.46,789.84 U3.6@796.46,834.03
  Top Layer w10: v1@1460,1350 1480.16,1329.84 U5.6@1499.6,1329.84
  Bottom Layer w8: v1(777.17,737.25) 777.17,708.28 824.82,660.63 1352.64,660.63 1423.92,731.91 1423.92,917.45 1460,953.53 v1(1460,1355)
GND: C1.2 C2.2 C3.2 C4.2 C5.2 C6.1 C7.1 C8.1 C9.2 C10.2 C11.2 C12.2 C13.2 C14.2 C15.2 C16.2 C17.2 C18.2 C19.2 D1.2 D2.3 D2.8 D3.3 D3.8 J1.5 J2.3 R4.1 R5.1 R10.1 R12.1 U1.2 U2.4 U3.10 U3.12 U3.27 U3.37 U3.44 U3.49 U4.7 U4.9 U5.7 U5.9 Y1.2 Y1.4 | length 2646.8
  Top Layer w8: v1(591.68,925.92) 604.12,938.36 U3.44@672.44,938.36
  Top Layer w10: v1@181.61,1284.03 v1(183.65,1281.99) ; C2.2@181.61,1329.84 190.88,1339.11 C1.2@237.8,1339.11 256.01,1339.11 257.72,1340.82 257.72,1341.84 279.95,1364.08 U1.2@297.35,1364.08 ; J1.5@187.51,1113.58 227.21,1113.58 v1(239.75,1126.12) ; U2.4@328.5,1070.16 v1(328.5,1096.78) ; C3.2@431.14,1331.74 476.82,1331.74 v1(476.98,1331.59) ; Y1.4@552.01,861.3 552.01,871.36 591.68,911.02 v1(591.68,925.92) ; v1(649.63,1104.38) 649.63,1083.75 657.22,1076.16 U3.37@672.44,1076.16 ; v1(854.81,794.5) 875.2,814.89 U3.10@875.2,834.03 ; U3.27@875.2,1101.75 875.2,1122.44 891.54,1138.78 899.76,1138.78 911.33,1150.35 C12.2@911.33,1171.37 ; v1@911.33,1202.98 v1(912.28,1203.93) ; U3.12@914.57,834.03 954.76,834.03 ; C10.2@1019.65,809.79 C10.2@1021.53,811.67 ; v1(1053.32,1666.71) v1@1055.3,1668.69 ; v1@1055.3,1437.51 v1(1055.81,1438.03) ; v1@1056.68,811.67 v1(1056.97,811.96) ; C18.2@1435,1305 1438.62,1308.62 1440.16,1310.16 U5.7@1499.6,1310.16 ; C16.2@1438.16,865.41 U4.7@1497.6,865.41
  Top Layer w15: R5.1@160.5,813 v1(213.76,813) ; v1@181.61,1284.03 C2.2@181.61,1329.84 ; v1(288.1,732.72) 290.51,735.13 C4.2@290.51,791.02 ; C5.2@334.7,951.59 v1(381.52,951.59) ; C7.1@399.42,799.32 399.42,754.01 v1(401.69,751.75) ; v1(439.34,690.6) 439.76,690.17 C6.1@491.68,690.17 479.18,702.67 Y1.2@479.18,770.75 ; v1(441.64,981.82) C9.2@484.12,981.82 ; v1@442.65,933.41 C11.2@484.83,933.41 ; R4.1@529.2,1133.82 571.55,1133.82 v1(571.96,1134.24) ; v1(647.13,640.82) 649.76,643.45 C8.1@649.76,683.1 ; v1(732.33,1440.24) 733.3,1439.27 D3.3@733.3,1356.04 ; D3.8@733.3,1749.74 733.3,1665.85 v1(734.51,1664.64) ; C15.2@816.3,712.27 851.71,712.27 v1(854.26,709.72) ; C13.2@895.61,711.75 903.06,704.29 942.4,704.29 C14.2@954.3,692.39 995.12,692.39 v1(997.7,694.98) ; 954.76,834.03 979,809.79 C10.2@1019.65,809.79 ; C10.2@1021.53,811.67 v1@1056.68,811.67 ; D2.3@1055.3,1356.04 v1@1055.3,1437.51 ; v1@1055.3,1668.69 D2.8@1055.3,1749.74 ; v1(1388,905.25) 1388,863.87 C16.2@1436.62,863.87 ; v1(1390,1350) 1390,1308.62 C18.2@1438.62,1308.62 ; C17.2@1519.38,765.25 1519.38,788.09 1535,803.71 v2(1535,859.5) ; C19.2@1521.38,1210 1521.38,1232.84 1537,1248.46 v2(1537,1304.25) U5.9@1537,1320 ; v1(1547.5,1089.22) 1573.96,1062.77 R10.1@1573.96,1004.23 ; v1(1551.11,1556.54) 1574.39,1533.26 R12.1@1574.39,1453.37
  Top Layer w20: D1.2@200.96,1510.49 200.96,1525.42 201.06,1525.52 v1(201.06,1575.17) ; C12.2@911.33,1171.37 v1@911.33,1202.98
  other v1: 442.05,934.01
  other v2: 774.66,876.36 837.93,876.36 1535,891 714.76,936.26 774.66,936.26 837.93,936.26 897.83,936.26 714.76,999.52 774.66,999.52 837.93,999.52 897.83,999.52 774.66,1059.43 837.93,1059.43 1537,1335.75
JTAG_RST: C8.2 J2.1 R6.2 U3.48 | length 426.9
  Top Layer w8: U3.48@672.44,859.62 672.44,824.36 647.13,799.05 649.76,796.42 C8.2@649.76,746.09 687.54,746.09 705.29,728.34 R6.2@705.29,725.64 736.5,725.64 751.56,710.58 751.56,696.68 751.62,696.62 J2.1@751.62,526.92
JTAG_TEST: J2.2 U3.47 | length 424.6
  Top Layer w10: v1(633.43,864.02) 648.72,879.31 U3.47@672.44,879.31
  Bottom Layer w8: v1(633.43,864.02) 633.43,856.85 610.06,833.48 610.06,613.09 650.34,572.82 J2.2@650.34,511.15
LC-A: C17.1 U4.1 U4.2 U4.3 | length 39382.5
  Top Layer w4: 2035.22,654.92 2314.43,841.9 2271.31,922.57 1990.45,806.16 ccw(c2630,1062.4) 2057.14,679.63 2303.25,844.07 2266.94,912.01 2000.87,801.78 ccw(c2630,1062.4) 2059.36,690.78 2292.2,846.35 2262.69,901.56 2011.38,797.44 ccw(c2630,1062.4) 2061.67,701.98 2281.29,848.7 2258.59,891.19 2021.97,793.15 ccw(c2630,1062.4) 2064.08,713.22 2270.51,851.13 2254.61,880.88 2032.66,788.9 ccw(c2630,1062.4) 2066.57,724.51 2259.85,853.61 2250.75,870.64 2043.43,784.72 ccw(c2630,1062.4) 2069.16,735.85 2235.95,847.22 cw(c2630,1062.4) 2232.14,854.34 ; v3(2078.1,768.49) 2064.05,761.49 cw(c2630,1062.4) 2054.31,780.57 2232.16,854.3 ; 2112.33,575.33 2131.47,575.33 ccw(c2630,1062.4) 2249.53,478.43 2422.83,737.92 2352.13,795.95 2137.19,580.92 ccw(c2630,1062.4) 2247.23,489.54 2411.67,735.65 2352.12,784.52 2148.49,580.86 ccw(c2630,1062.4) 2245.02,500.69 2400.59,733.53 2352.2,773.25 2159.87,580.87 ccw(c2630,1062.4) 2242.86,511.93 2389.62,731.53 2352.38,762.09 2171.29,580.96 ccw(c2630,1062.4) 2240.78,523.23 2378.73,729.64 2352.65,751.04 2182.79,581.13 ccw(c2630,1062.4) 2238.76,534.62 2367.93,727.85 2353,740.1 2194.35,581.38 ccw(c2630,1062.4) 2236.82,546.09 2348.29,712.8 cw(c2630,1062.4) 2342.05,717.92 2205.98,581.72 ccw(c2630,1062.4) 2222.28,567.82 v3(2232.59,579.66)
  Top Layer w10: U4.1@1568.62,841.94 C17.1@1568.62,770 1749.17,589.45 v6(1791,589.45) ; U4.2@1572.4,865.41 1609.55,865.41 1647.83,827.13 1647.83,826.96 v4(1663.1,811.69) 1664.7,811.69 1901.07,575.33 2112.33,575.33 ; U4.3@1572.4,885.09 1662.5,885.09 v4(1663.03,884.56) 1663.56,885.09 1729.91,885.09 1960.08,654.92 2035.22,654.92
  Signal Layer 1 w4: v3@1993.89,723.04 cw(c2630,1062.4) 1960.74,794.26 2271.31,922.57 2314.43,841.9 2061.62,673 cw(c2630,1062.4) 1993.47,798.74 2266.94,912.01 2303.25,844.07 2063.79,684.07 ; 2063.77,684.1 cw(c2630,1062.4) 2003.98,794.4 2262.69,901.56 2292.2,846.35 2066,695.25 cw(c2630,1062.4) 2014.57,790.1 2258.59,891.19 2281.29,848.7 2068.32,706.44 cw(c2630,1062.4) 2025.25,785.86 2254.61,880.88 2270.51,851.13 2070.73,717.68 cw(c2630,1062.4) 2036.03,781.66 2250.75,870.64 2259.85,853.61 2073.23,728.97 cw(c2630,1062.4) 2046.9,777.5 2232.14,854.34 ccw(c2630,1062.4) 2235.95,847.22 ; v3(2078.1,768.49) 2064.05,761.49 ccw(c2630,1062.4) 2075.82,740.31 2235.85,847.16 ; v3@2172.17,505.44 cw(c2630,1062.4) 2114.3,558.55 2352.13,795.95 2422.83,737.92 2253.9,485.13 cw(c2630,1062.4) 2142.82,575.22 2352.12,784.52 2411.67,735.65 2251.67,496.19 cw(c2630,1062.4) 2154.19,575.23 2352.2,773.25 2400.59,733.53 2249.43,507.36 cw(c2630,1062.4) 2165.62,575.32 2352.38,762.09 2389.62,731.53 2247.29,518.59 cw(c2630,1062.4) 2177.12,575.48 2352.65,751.04 2378.73,729.64 2245.22,529.89 cw(c2630,1062.4) 2188.68,575.72 2353,740.1 2367.93,727.85 2243.21,541.28 cw(c2630,1062.4) 2200.31,576.05 2342.05,717.92 ccw(c2630,1062.4) 2348.29,712.8 2241.26,552.76 cw(c2630,1062.4) 2222.28,567.82 v3(2232.59,579.66)
  Signal Layer 2 w4: v3@1993.89,723.04 ccw(c2630,1062.4) 2035.22,654.92 2314.43,841.9 2271.31,922.57 1990.45,806.16 ccw(c2630,1062.4) 2057.14,679.63 2303.25,844.07 2266.94,912.01 2000.87,801.78 ccw(c2630,1062.4) 2059.36,690.78 2292.2,846.35 2262.69,901.56 2011.38,797.44 ccw(c2630,1062.4) 2061.67,701.98 2281.29,848.7 2258.59,891.19 2021.97,793.15 ccw(c2630,1062.4) 2064.08,713.22 2270.51,851.13 2254.61,880.88 2032.66,788.9 ccw(c2630,1062.4) 2066.57,724.51 2259.85,853.61 2250.75,870.64 2043.43,784.72 ccw(c2630,1062.4) 2069.16,735.85 2235.95,847.22 cw(c2630,1062.4) 2232.14,854.34 ; v3@2100.91,779.44 cw(c2630,1062.4) 2092.24,796.29 2232.16,854.3 ; v3@2172.17,505.44 ccw(c2630,1062.4) 2236.43,458.32 2422.83,737.92 2352.13,795.95 2137.19,580.92 ccw(c2630,1062.4) 2247.23,489.54 2411.67,735.65 2352.12,784.52 2148.49,580.86 ccw(c2630,1062.4) 2245.02,500.69 2400.59,733.53 2352.2,773.25 2159.87,580.87 ccw(c2630,1062.4) 2242.86,511.93 2389.62,731.53 2352.38,762.09 2171.29,580.96 ccw(c2630,1062.4) 2240.78,523.23 2378.73,729.64 2352.65,751.04 2182.79,581.13 ccw(c2630,1062.4) 2238.76,534.62 2367.93,727.85 2353,740.1 2194.35,581.38 ccw(c2630,1062.4) 2236.82,546.09 2348.29,712.8 cw(c2630,1062.4) 2342.05,717.92 ; v3@2249.47,598.51 cw(c2630,1062.4) 2235.01,610.76 2342.13,717.94
  Bottom Layer w4: 1960.74,794.26 2271.31,922.57 2314.43,841.9 2061.62,673 cw(c2630,1062.4) 1993.47,798.74 2266.94,912.01 2303.25,844.07 2063.79,684.07 ; 2063.77,684.1 cw(c2630,1062.4) 2003.98,794.4 2262.69,901.56 2292.2,846.35 2066,695.25 cw(c2630,1062.4) 2014.57,790.1 2258.59,891.19 2281.29,848.7 2068.32,706.44 cw(c2630,1062.4) 2025.25,785.86 2254.61,880.88 2270.51,851.13 2070.73,717.68 cw(c2630,1062.4) 2036.03,781.66 2250.75,870.64 2259.85,853.61 2073.23,728.97 cw(c2630,1062.4) 2046.9,777.5 2232.14,854.34 ccw(c2630,1062.4) 2235.95,847.22 2109.98,763.1 cw(c2630,1062.4) v3@2100.91,779.44 ; 2104,547.86 2131.47,575.33 2352.13,795.95 2422.83,737.92 2253.9,485.13 cw(c2630,1062.4) 2142.82,575.22 2352.12,784.52 2411.67,735.65 2251.67,496.19 cw(c2630,1062.4) 2154.19,575.23 2352.2,773.25 2400.59,733.53 2249.43,507.36 cw(c2630,1062.4) 2165.62,575.32 2352.38,762.09 2389.62,731.53 2247.29,518.59 cw(c2630,1062.4) 2177.12,575.48 2352.65,751.04 2378.73,729.64 2245.22,529.89 cw(c2630,1062.4) 2188.68,575.72 2353,740.1 2367.93,727.85 2243.21,541.28 cw(c2630,1062.4) 2200.31,576.05 2342.05,717.92 ccw(c2630,1062.4) 2348.29,712.8 2264.1,586.88 cw(c2630,1062.4) v3@2249.47,598.51
  Bottom Layer w10: 1960.74,794.26 1928,761.51 1928,614 1903,589 1791.45,589 1791.45,564 1807.59,547.86 2104,547.86
  other v3: 2171.87,505.07 2249.63,598.7 1993.46,722.81 2101.13,779.56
